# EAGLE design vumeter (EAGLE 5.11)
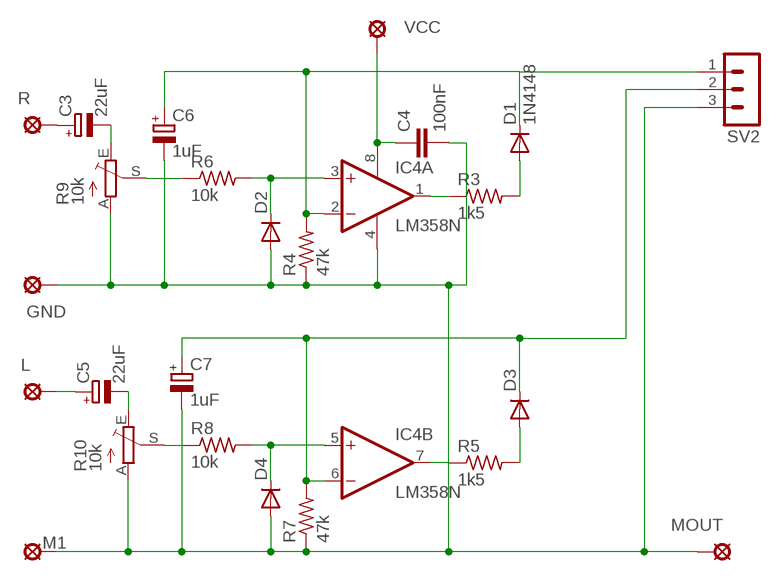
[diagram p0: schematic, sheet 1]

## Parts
C3  22uF  CPOL-EUE2.5-5  [E2,5-5]
C4  100nF  C-EU050-025X075  [C050-025X075]
C5  22uF  CPOL-EUE2.5-5  [E2,5-5]
C6  1uF  CPOL-EUE2.5-5  [E2,5-5]
C7  1uF  CPOL-EUE2.5-5  [E2,5-5]
D1  1N4148  1N4004  [DO41-10]
D2  1N4004  [DO41-10]
D3  1N4004  [DO41-10]
D4  1N4004  [DO41-10]
GND  SE11  [SE11]
IC4  LM358N  [DIL08]
L  SE11  [SE11]
M1  SE11  [SE11]
MOUT  SE11  [SE11]
R  SE11  [SE11]
R3  1k5  R-US_0207/10  [0207/10]
R4  47k  R-US_0207/10  [0207/10]
R5  1k5  R-US_0207/10  [0207/10]
R6  10k  R-US_0207/10  [0207/10]
R7  47k  R-US_0207/10  [0207/10]
R8  10k  R-US_0207/10  [0207/10]
R9  10k  TRIM_EU-LI10  [LI10]
R10  10k  TRIM_EU-LI10  [LI10]
SV2  MA03-1  [MA03-1]
VCC  SE11  [SE11]

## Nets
N$1: C4.1 IC4.8(P:V+) VCC.MP
N$3: C3.+ R.MP
N$26: C4.2 C6.- C7.- D2.A D4.A GND.MP IC4.4(P:V-) M1.MP MOUT.MP R4.1 R7.1 R9.A R10.A SV2.3
N$30: IC4.1(A:OUT) R3.1
N$31: D1.A R3.2
N$32: C5.+ L.MP
N$33: R6.1 R9.S
N$34: C6.+ D1.C IC4.2(A:-IN) R4.2 SV2.1
N$35: C3.- R9.E
N$36: D2.C IC4.3(A:+IN) R6.2
N$38: IC4.7(B:OUT) R5.1
N$39: D3.A R5.2
N$40: C7.+ D3.C IC4.6(B:-IN) R7.2 SV2.2
N$42: D4.C IC4.5(B:+IN) R8.2
N$43: R8.1 R10.S
N$44: C5.- R10.E

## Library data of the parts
C3 C5-C7 = resistor:CPOL-EU: POLARIZED CAPACITOR, European symbol
C4 = resistor:C-EU: CAPACITOR, European symbol
D1-D4 = diode:1N4004: DIODE
GND L M1 MOUT R VCC = solpad:SE11: SOLDER PAD
IC4 = linear:LM358: OP AMP also LM158; LM258; LM2904 Source: http://cache.national.com/ds/LM/LM158.pdf
R3-R8 = resistor:R-US_: RESISTOR, American symbol
R9 R10 = pot:TRIM_EU-: POTENTIOMETER
SV2 = con-lstb:MA03-1: PIN HEADER; OC_FARNELL: unknown; OC_NEWARK: unknown

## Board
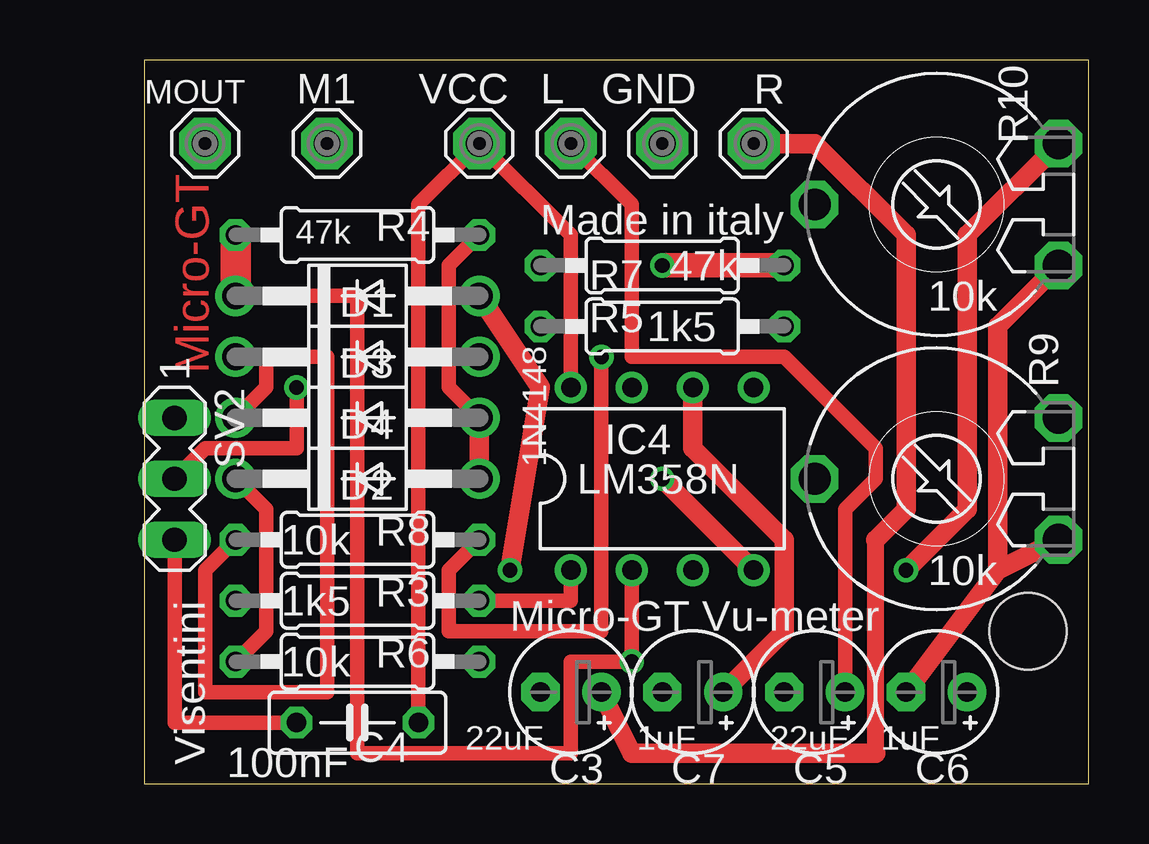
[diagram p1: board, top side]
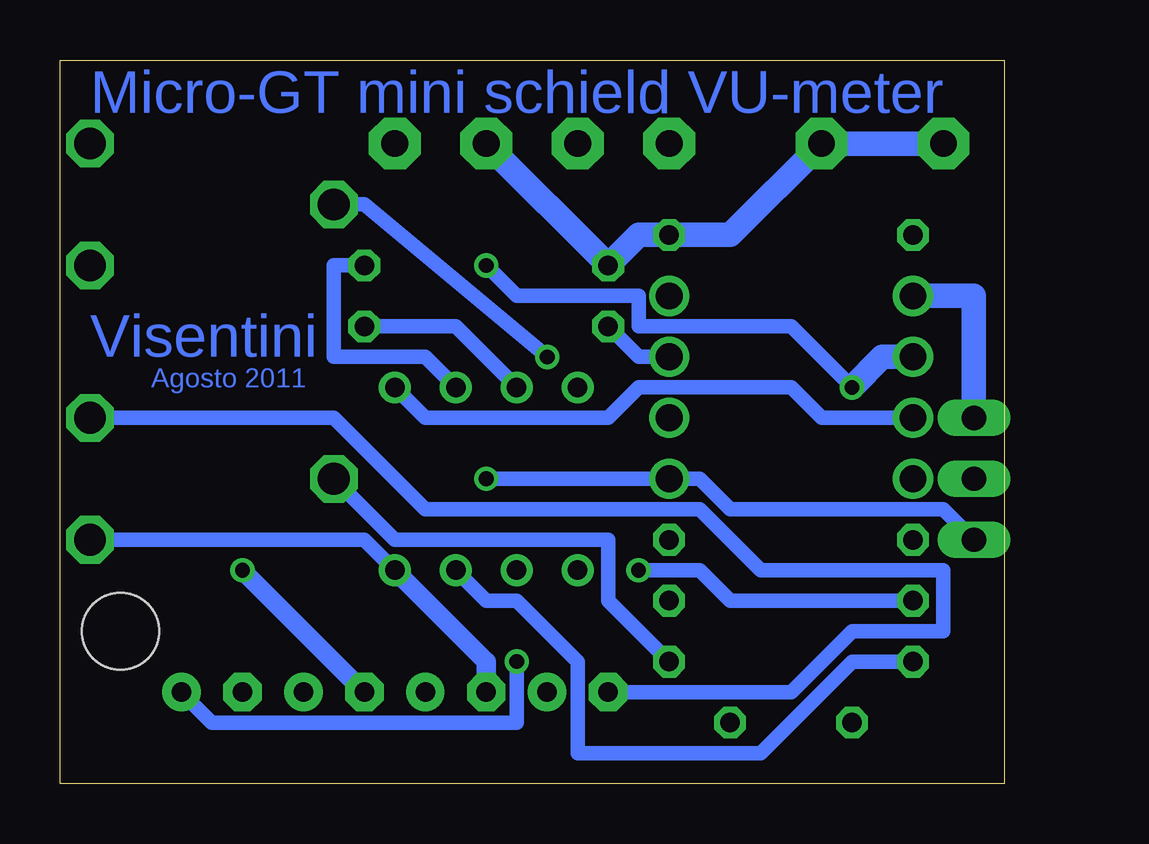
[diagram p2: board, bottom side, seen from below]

Size 39.35 x 30.15 mm. Coordinates in mm from the lower left corner, seen from the top.
Outline: 0,0 39.35,0 39.35,30.15 0,30.15 0,0
Copper layers (1*16): Top 0.035mm / dielectric 1.5mm / Bottom 0.035mm
Design rules "default": minimum track width 10mil, minimum drill 24mil, track to track 8mil, track to pad 8mil, pad to pad 8mil, via to via 8mil, smd to smd 8mil, copper to edge 40mil, drill to drill 8mil, minimum pad ring 10mil, minimum via ring 8mil, stop-mask expansion 4mil, vias tented up to drill 0mil, thermal gap 10mil
Holes 3.2 mm at 36.83,6.35

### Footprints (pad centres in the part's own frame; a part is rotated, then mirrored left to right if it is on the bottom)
E2,5-5 = drill 0.813 pad 1.6 round: + -1.27,0 | drill 0.813 pad 1.6 octagon: - 1.27,0
C050-025X075 = drill 0.813 octagon: 1 -2.54,0; 2 2.54,0
DO41-10 = drill 1.118 round: A 5.08,0; C -5.08,0
SE11 = drill 1.118 pad 2.159 octagon: MP 0,0
DIL08 = drill 0.813 pad 1.27 round: 1 -3.81,-3.81; 2 -1.27,-3.81; 3 1.27,-3.81; 4 3.81,-3.81; 5 3.81,3.81; 6 1.27,3.81; 7 -1.27,3.81; 8 -3.81,3.81
0207/10 = drill 0.813 octagon: 1 -5.08,0; 2 5.08,0
LI10 = drill 1.321 octagon: A -2.54,-5.08; E 2.54,-5.08; S 0,5.08
MA03-1 = drill 1.016 long: 1 -2.54,0; 2 0,0; 3 2.54,0

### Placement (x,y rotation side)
C3  17.78,3.81 180 top
C4  8.89,2.54 180 top
C5  27.94,3.81 180 top
C6  33.02,3.81 180 top
C7  22.86,3.81 180 top
D1  8.89,20.32 0 top
D2  8.89,12.7 0 top
D3  8.89,17.78 0 top
D4  8.89,15.24 0 top
GND  21.59,26.67 0 top
IC4  21.59,12.7 0 top
L  17.78,26.67 0 top
M1  7.62,26.67 0 top
MOUT  2.54,26.67 0 top
R  25.4,26.67 0 top
R3  8.89,7.62 180 top
R4  8.89,22.86 180 top
R5  21.59,19.05 180 top
R6  8.89,5.08 180 top
R7  21.59,21.59 0 top
R8  8.89,10.16 180 top
R9  33.02,12.7 90 top
R10  33.02,24.13 90 top
SV2  1.27,12.7 270 top
VCC  13.97,26.67 0 top

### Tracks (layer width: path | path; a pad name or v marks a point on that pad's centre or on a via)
N$1
  Top 0.61: C4.1 11.43,24.13 VCC.MP 17.78,22.86 IC4.8
N$3
  Top 0.711: 30.48,1.27 30.48,10.16
  Top 0.813: C3.+ 20.32,1.27 30.48,1.27 | 30.48,10.16 31.75,11.43 31.75,22.86 27.94,26.67 R.MP
N$26  (via drill 0.61)
  Top 0.61: C4.2 1.27,2.54 SV2.3 | D4.A 12.7,16.51 12.7,21.59 R4.1
  Top 0.813: R9.A 35.56,8.89 | 35.56,8.89 C6.- | R10.A 35.56,19.05 35.56,8.89 | D2.A D4.A | v21.59,12.7 IC4.4
  Bottom 0.61: IC4.4 26.67,10.16 R9.A | SV2.3 2.54,11.43 11.43,11.43 12.7,12.7 D2.A v21.59,12.7
  Bottom 0.813: IC4.4 21.59,5.08 C7.-
  Bottom 1.016: MOUT.MP M1.MP 11.43,22.86 R4.1 15.24,22.86 R7.1 GND.MP
N$30
  Top 0.61: R3.1 17.78,7.62 IC4.1
N$31  (via drill 0.61)
  Top 0.813: v15.24,8.89 16.51,16.51 D1.A
  Bottom 0.61: R3.2 11.43,7.62 12.7,8.89 v15.24,8.89
N$32
  Top 0.61: C5.+ 29.21,11.43 30.48,12.7 30.48,13.97 26.67,17.78 20.32,17.78 20.32,24.13 L.MP
N$33
  Bottom 0.61: R6.1 16.51,7.62 16.51,10.16 25.4,10.16 R9.S
N$34  (via drill 0.61)
  Top 0.61: IC4.2 v20.32,5.08 17.78,5.08 17.78,1.27 8.89,1.27 8.89,20.32 D1.C
  Top 1.27: D1.C R4.2
  Bottom 0.61: v20.32,5.08 20.32,2.54 33.02,2.54 C6.+
  Bottom 1.016: SV2.1 1.27,20.32 D1.C
N$35
  Bottom 0.61: C3.- 8.89,3.81 6.35,6.35 2.54,6.35 2.54,8.89 10.16,8.89 12.7,11.43 24.13,11.43 27.94,15.24 R9.E
N$36
  Top 0.61: R6.2 5.08,6.35 5.08,11.43 D2.C
  Bottom 0.61: IC4.3 21.59,7.62 20.32,7.62 17.78,5.08 17.78,1.27 10.16,1.27 6.35,5.08 R6.2
N$38
  Bottom 0.61: IC4.7 22.86,19.05 R5.1
N$39
  Bottom 0.61: R5.2 15.24,17.78 D3.A
N$40  (via drill 0.61)
  Top 0.61: SV2.2 2.54,13.97 6.35,13.97 v6.35,16.51
  Top 0.813: C7.+ 26.67,6.35 26.67,10.16 22.86,13.97 IC4.6
  Top 1.016: v21.59,21.59 R7.2
  Bottom 0.61: IC4.6 24.13,17.78 27.94,17.78 27.94,21.59 R7.2 | v6.35,16.51 8.89,19.05 15.24,19.05 15.24,20.32 20.32,20.32 v21.59,21.59
  Bottom 1.016: v6.35,16.51 5.08,17.78 D3.C
N$42
  Top 0.61: R8.2 2.54,8.89 2.54,3.81 7.62,3.81 7.62,17.78 5.08,17.78 5.08,16.51 D4.C
  Bottom 0.61: IC4.5 24.13,15.24 16.51,15.24 15.24,16.51 8.89,16.51 7.62,15.24 D4.C
N$43  (via drill 0.61)
  Top 0.61: R8.1 12.7,8.89 12.7,6.35 19.05,6.35 v19.05,17.78
  Bottom 0.61: v19.05,17.78 26.67,24.13 R10.S
N$44  (via drill 0.61)
  Top 0.813: v31.75,8.89 34.29,11.43 34.29,22.86 R10.E
  Bottom 0.813: C5.- v31.75,8.89

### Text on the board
Top: Micro-GT
Bottom: Micro-GT mini schield VU-meter | Visentini | Agosto 2011
tNames: Made in italy | Visentini | Micro-GT Vu-meter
